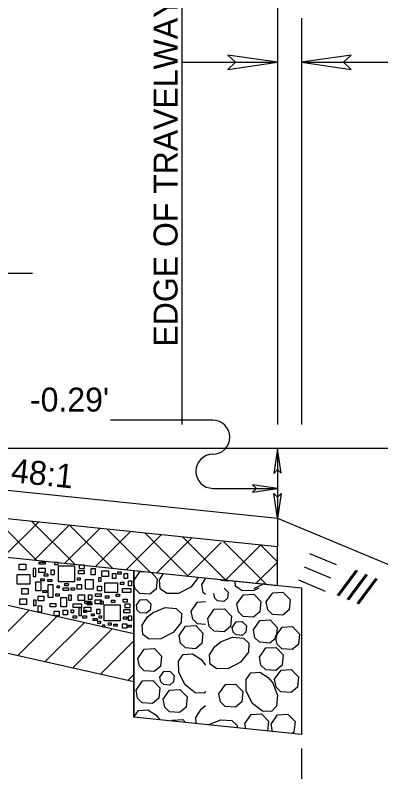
# Model space of a CAD drawing. Extents: x 6561 to 6787, y 19927 to 20919.
# Drawn here: x 6709.58 to 6717.22, y 20861.89 to 20877.71 of the extents above; entities that cross this region are included whole.
import ezdxf

# ---------------------------------------------------------------- set-up
doc = ezdxf.new("R2010")
doc.units = 0
for name, color, linetype in [('Level 1', 7, 'Continuous'), ('Level 10', 7, 'Continuous'), ('Level 3', 7, 'Continuous'), ('Level 4', 7, 'Continuous'), ('Level 5', 7, 'Continuous'), ('Level 7', 7, 'Continuous'), ('Level 8', 7, 'Continuous')]:
    doc.layers.add(name, color=color, linetype=linetype)

msp = doc.modelspace()

# ---------------------------------------------------------------- linework, layer by layer
at = {"layer": 'Level 1'}
for p, q in [((6713.057, 20879.65), (6713.057, 20869.15)), ((6715.057, 20879.65), (6715.057, 20869.15)), ((6715.557, 20877.65), (6715.557, 20869.15)), ((6713.057, 20876.726), (6715.057, 20876.726)), ((6715.557, 20876.726), (6717.557, 20876.726)), ((6703.419, 20872.316), (6709.936, 20872.316)), ((6713.708, 20869.242), (6711.572, 20869.242)), ((6779.047, 20868.65), (6628.473, 20868.65)), ((6715.057, 20868.65), (6715.057, 20867.192)), ((6713.708, 20867.817), (6715.057, 20867.817)), ((6715.557, 20862.377), (6715.557, 20854.582))]:
    msp.add_line(p, q, dxfattribs=at)
for points in [[(6715.057, 20876.726), (6714.018, 20876.876), (6714.178, 20876.726), (6714.018, 20876.576)], [(6715.557, 20876.726), (6716.596, 20876.576), (6716.436, 20876.726), (6716.596, 20876.876)], [(6715.057, 20868.65), (6714.985, 20868.13), (6715.059, 20868.211), (6715.135, 20868.131)], [(6715.057, 20867.817), (6714.537, 20867.889), (6714.618, 20867.815), (6714.538, 20867.739)], [(6715.057, 20867.192), (6714.985, 20867.711), (6715.059, 20867.631), (6715.135, 20867.711)]]:
    msp.add_lwpolyline(points, close=True, dxfattribs=at)
for centre, start, end in [((6713.708, 20868.886), 270, 90), ((6713.708, 20868.173), 90, 270)]:
    msp.add_arc(centre, 0.356, start, end, dxfattribs=at)
at = {"layer": 'Level 10'}
for p, q in [((6712.057, 20864.778), (6701.057, 20867.246)), ((6701.057, 20866.246), (6712.057, 20863.778)), ((6712.057, 20866.1), (6712.057, 20863.033)), ((6709.052, 20864.452), (6709.869, 20865.268)), ((6709.63, 20864.322), (6710.446, 20865.139)), ((6710.207, 20864.193), (6711.024, 20865.009)), ((6710.785, 20864.063), (6711.602, 20864.88)), ((6712.057, 20863.778), (6712.057, 20864.778)), ((6711.362, 20863.933), (6712.057, 20864.628)), ((6711.94, 20863.804), (6712.057, 20863.921))]:
    msp.add_line(p, q, dxfattribs=at)
at = {"layer": 'Level 3'}
for p, q in [((6715.057, 20866.592), (6701.057, 20868.05)), ((6701.057, 20867.246), (6715.057, 20865.787)), ((6710.031, 20866.311), (6709.134, 20867.209)), ((6710.063, 20867.112), (6709.335, 20866.383)), ((6710.821, 20866.229), (6709.923, 20867.126)), ((6710.703, 20867.045), (6709.975, 20866.317)), ((6711.61, 20866.146), (6710.712, 20867.044)), ((6711.344, 20866.978), (6710.615, 20866.25)), ((6711.984, 20866.912), (6711.256, 20866.183)), ((6712.399, 20866.064), (6711.501, 20866.962)), ((6712.625, 20866.845), (6711.896, 20866.116)), ((6713.189, 20865.982), (6712.291, 20866.88)), ((6713.265, 20866.778), (6712.537, 20866.05)), ((6713.966, 20865.912), (6713.08, 20866.797)), ((6713.881, 20866.687), (6713.177, 20865.983)), ((6714.821, 20865.812), (6713.923, 20866.71)), ((6714.703, 20866.628), (6713.975, 20865.9)), ((6715.057, 20866.283), (6714.712, 20866.627)), ((6715.057, 20865.787), (6715.057, 20866.592)), ((6715.057, 20866.275), (6714.615, 20865.833))]:
    msp.add_line(p, q, dxfattribs=at)
at = {"layer": 'Level 4'}
for p, q in [((6701.057, 20867.246), (6712.057, 20866.1)), ((6712.057, 20864.778), (6701.057, 20867.246)), ((6712.057, 20866.1), (6712.057, 20864.778))]:
    msp.add_line(p, q, dxfattribs=at)
for points in [[(6710.206, 20866.229), (6710.077, 20866.229), (6710.077, 20866.276), (6710.206, 20866.276)], [(6710.399, 20866.221), (6710.473, 20866.221), (6710.473, 20866.268), (6710.399, 20866.268)], [(6709.663, 20866.232), (6709.8, 20866.232), (6709.8, 20866.114), (6709.663, 20866.114)], [(6710.01, 20866.138), (6709.951, 20866.138), (6709.951, 20865.973), (6710.01, 20865.973)], [(6710.069, 20866.15), (6710.202, 20866.15), (6710.202, 20866.056), (6710.069, 20866.056)], [(6710.324, 20866.017), (6710.399, 20866.017), (6710.399, 20866.103), (6710.324, 20866.103)], [(6710.485, 20866.197), (6710.819, 20866.197), (6710.819, 20865.863), (6710.485, 20865.863)], [(6711.019, 20866.032), (6710.897, 20866.032), (6710.897, 20866.099), (6711.019, 20866.099)], [(6711.027, 20866.213), (6710.917, 20866.213), (6710.917, 20866.142), (6711.027, 20866.142)], [(6711.251, 20866.005), (6711.164, 20866.005), (6711.164, 20866.138), (6711.251, 20866.138)], [(6711.387, 20866.094), (6711.525, 20866.094), (6711.525, 20865.976), (6711.387, 20865.976)], [(6709.882, 20865.816), (6709.615, 20865.816), (6709.615, 20866.016), (6709.882, 20866.016)], [(6710.185, 20866.029), (6710.256, 20866.029), (6710.256, 20865.982), (6710.185, 20865.982)], [(6710.882, 20865.946), (6710.937, 20865.946), (6710.937, 20865.899), (6710.882, 20865.899)], [(6711.325, 20865.954), (6711.369, 20865.954), (6711.369, 20865.867), (6711.325, 20865.867)], [(6711.614, 20866.033), (6711.681, 20866.033), (6711.681, 20865.931), (6711.614, 20865.931)], [(6711.725, 20866.068), (6711.795, 20866.068), (6711.795, 20866.021), (6711.725, 20866.021)], [(6711.857, 20866.033), (6711.924, 20866.033), (6711.924, 20865.931), (6711.857, 20865.931)], [(6710.112, 20865.675), (6710.01, 20865.675), (6710.01, 20865.859), (6710.112, 20865.859)], [(6710.115, 20865.927), (6710.185, 20865.927), (6710.185, 20865.88), (6710.115, 20865.88)], [(6710.257, 20865.914), (6710.34, 20865.914), (6710.34, 20865.871), (6710.257, 20865.871)], [(6710.269, 20865.804), (6710.363, 20865.804), (6710.363, 20865.533), (6710.269, 20865.533)], [(6710.454, 20865.781), (6710.493, 20865.781), (6710.493, 20865.734), (6710.454, 20865.734)], [(6710.613, 20865.825), (6710.684, 20865.825), (6710.684, 20865.777), (6710.613, 20865.777)], [(6710.96, 20865.71), (6710.87, 20865.71), (6710.87, 20865.804), (6710.96, 20865.804)], [(6711.043, 20865.911), (6711.204, 20865.911), (6711.204, 20865.71), (6711.043, 20865.71)], [(6711.718, 20865.639), (6711.451, 20865.639), (6711.451, 20865.84), (6711.718, 20865.84)], [(6711.779, 20865.852), (6711.85, 20865.852), (6711.85, 20865.805), (6711.779, 20865.805)], [(6711.944, 20865.884), (6712.01, 20865.884), (6712.01, 20865.781), (6711.944, 20865.781)], [(6709.714, 20865.721), (6709.851, 20865.721), (6709.851, 20865.603), (6709.714, 20865.603)], [(6710.158, 20865.683), (6710.229, 20865.683), (6710.229, 20865.636), (6710.158, 20865.636)], [(6710.693, 20865.679), (6710.579, 20865.679), (6710.579, 20865.734), (6710.693, 20865.734)], [(6710.747, 20865.738), (6710.817, 20865.738), (6710.817, 20865.691), (6710.747, 20865.691)], [(6711.384, 20865.675), (6711.294, 20865.675), (6711.294, 20865.769), (6711.384, 20865.769)], [(6711.991, 20865.642), (6711.823, 20865.642), (6711.823, 20865.721), (6711.991, 20865.721)], [(6709.674, 20865.509), (6709.812, 20865.509), (6709.812, 20865.391), (6709.674, 20865.391)], [(6709.967, 20865.486), (6710.01, 20865.486), (6710.01, 20865.36), (6709.967, 20865.36)], [(6710.175, 20865.466), (6710.057, 20865.466), (6710.057, 20865.561), (6710.175, 20865.561)], [(6710.425, 20865.612), (6710.496, 20865.612), (6710.496, 20865.565), (6710.425, 20865.565)], [(6710.528, 20865.537), (6710.65, 20865.537), (6710.65, 20865.337), (6710.528, 20865.337)], [(6710.748, 20865.474), (6710.701, 20865.474), (6710.701, 20865.588), (6710.748, 20865.588)], [(6710.89, 20865.588), (6711.027, 20865.588), (6711.027, 20865.47), (6710.89, 20865.47)], [(6711.109, 20865.592), (6711.176, 20865.592), (6711.176, 20865.49), (6711.109, 20865.49)], [(6711.372, 20865.4), (6711.251, 20865.4), (6711.251, 20865.486), (6711.372, 20865.486)], [(6711.255, 20865.608), (6711.372, 20865.608), (6711.372, 20865.557), (6711.255, 20865.557)], [(6711.461, 20865.569), (6711.532, 20865.569), (6711.532, 20865.522), (6711.461, 20865.522)], [(6711.587, 20865.479), (6711.658, 20865.479), (6711.658, 20865.432), (6711.587, 20865.432)], [(6711.689, 20865.601), (6711.76, 20865.601), (6711.76, 20865.553), (6711.689, 20865.553)], [(6711.834, 20865.498), (6711.917, 20865.498), (6711.917, 20865.435), (6711.834, 20865.435)], [(6710.057, 20865.36), (6710.128, 20865.36), (6710.128, 20865.231), (6710.057, 20865.231)], [(6710.426, 20865.337), (6710.305, 20865.337), (6710.305, 20865.411), (6710.426, 20865.411)], [(6710.96, 20865.325), (6710.791, 20865.325), (6710.791, 20865.404), (6710.96, 20865.404)], [(6710.963, 20865.321), (6710.904, 20865.321), (6710.904, 20865.156), (6710.963, 20865.156)], [(6711.022, 20865.333), (6711.155, 20865.333), (6711.155, 20865.239), (6711.022, 20865.239)], [(6711.159, 20865.412), (6711.03, 20865.412), (6711.03, 20865.459), (6711.159, 20865.459)], [(6711.176, 20865.384), (6711.082, 20865.384), (6711.082, 20865.427), (6711.176, 20865.427)], [(6711.352, 20865.404), (6711.426, 20865.404), (6711.426, 20865.451), (6711.352, 20865.451)], [(6711.438, 20865.38), (6711.772, 20865.38), (6711.772, 20865.046), (6711.438, 20865.046)], [(6711.98, 20865.396), (6711.87, 20865.396), (6711.87, 20865.325), (6711.98, 20865.325)], [(6710.391, 20865.25), (6710.493, 20865.25), (6710.493, 20865.152), (6710.391, 20865.152)], [(6710.67, 20865.172), (6710.579, 20865.172), (6710.579, 20865.266), (6710.67, 20865.266)], [(6710.799, 20865.215), (6710.748, 20865.215), (6710.748, 20865.278), (6710.799, 20865.278)], [(6710.786, 20865.149), (6710.857, 20865.149), (6710.857, 20865.101), (6710.786, 20865.101)], [(6710.994, 20865.152), (6711.065, 20865.152), (6711.065, 20865.105), (6710.994, 20865.105)], [(6711.015, 20865.27), (6711.07, 20865.27), (6711.07, 20865.223), (6711.015, 20865.223)], [(6711.172, 20865.195), (6711.227, 20865.195), (6711.227, 20865.148), (6711.172, 20865.148)], [(6711.277, 20865.2), (6711.352, 20865.2), (6711.352, 20865.286), (6711.277, 20865.286)], [(6711.329, 20865.148), (6711.384, 20865.148), (6711.384, 20865.101), (6711.329, 20865.101)], [(6711.972, 20865.215), (6711.85, 20865.215), (6711.85, 20865.282), (6711.972, 20865.282)], [(6711.944, 20865.153), (6712.01, 20865.153), (6712.01, 20865.05), (6711.944, 20865.05)], [(6711.21, 20865.097), (6711.293, 20865.097), (6711.293, 20865.054), (6711.21, 20865.054)], [(6711.302, 20865.038), (6711.357, 20865.038), (6711.357, 20864.991), (6711.302, 20864.991)], [(6711.526, 20865.003), (6711.581, 20865.003), (6711.581, 20864.955), (6711.526, 20864.955)], [(6711.913, 20864.893), (6711.823, 20864.893), (6711.823, 20864.987), (6711.913, 20864.987)], [(6711.842, 20865.129), (6711.913, 20865.129), (6711.913, 20865.082), (6711.842, 20865.082)], [(6711.406, 20864.964), (6711.446, 20864.964), (6711.446, 20864.917), (6711.406, 20864.917)], [(6711.638, 20864.98), (6711.709, 20864.98), (6711.709, 20864.932), (6711.638, 20864.932)], [(6711.946, 20864.959), (6712.001, 20864.959), (6712.001, 20864.912), (6711.946, 20864.912)]]:
    msp.add_lwpolyline(points, close=True, dxfattribs=at)
at = {"layer": 'Level 5'}
for p, q in [((6712.057, 20863.033), (6712.057, 20866.1)), ((6712.057, 20866.1), (6715.557, 20865.735)), ((6715.557, 20865.735), (6715.557, 20862.669)), ((6715.557, 20862.669), (6712.057, 20863.033))]:
    msp.add_line(p, q, dxfattribs=at)
for points in [[(6712.048, 20865.879), (6712.183, 20866.071), (6712.283, 20866.076)], [(6712.417, 20866.062), (6712.547, 20865.928), (6712.525, 20865.711), (6712.393, 20865.601), (6712.181, 20865.616), (6712.081, 20865.713), (6712.049, 20865.879)], [(6713.41, 20865.959), (6713.246, 20865.749), (6712.988, 20865.62), (6712.746, 20865.616), (6712.609, 20865.713), (6712.596, 20865.906), (6712.679, 20866.035)], [(6713.475, 20865.808), (6713.557, 20865.925)], [(6713.557, 20865.594), (6713.508, 20865.642), (6713.475, 20865.808)], [(6714.03, 20865.894), (6714.011, 20865.878), (6713.883, 20865.887), (6713.858, 20865.912)], [(6714.669, 20865.732), (6714.561, 20865.678), (6714.318, 20865.674), (6714.181, 20865.771), (6714.174, 20865.879)], [(6714.771, 20865.817), (6714.564, 20865.714)], [(6713.947, 20865.732), (6714.026, 20865.649), (6714.013, 20865.519), (6713.934, 20865.453), (6713.807, 20865.462), (6713.747, 20865.52), (6713.727, 20865.62)], [(6714.823, 20865.443), (6714.958, 20865.635), (6715.172, 20865.647), (6715.321, 20865.492), (6715.3, 20865.275), (6715.167, 20865.165), (6714.955, 20865.18), (6714.856, 20865.277), (6714.823, 20865.443)], [(6712.11, 20865.371), (6712.19, 20865.486), (6712.319, 20865.493), (6712.409, 20865.4), (6712.396, 20865.27), (6712.316, 20865.204), (6712.189, 20865.213), (6712.129, 20865.271), (6712.11, 20865.371)], [(6714.211, 20865.4), (6714.346, 20865.591), (6714.561, 20865.603), (6714.71, 20865.448), (6714.688, 20865.232), (6714.556, 20865.121), (6714.344, 20865.137), (6714.244, 20865.233), (6714.212, 20865.4)], [(6712.458, 20865.224), (6712.71, 20865.323), (6712.941, 20865.304), (6713.05, 20865.199), (6713.047, 20865.012), (6712.88, 20864.799), (6712.623, 20864.67), (6712.38, 20864.666), (6712.243, 20864.763), (6712.23, 20864.956), (6712.341, 20865.129), (6712.468, 20865.23)], [(6713.255, 20865.248), (6713.389, 20865.44), (6713.557, 20865.449)], [(6713.557, 20864.973), (6713.387, 20864.985), (6713.287, 20865.082), (6713.255, 20865.248)], [(6713.6, 20865.095), (6713.734, 20865.287), (6713.949, 20865.299), (6714.098, 20865.144), (6714.076, 20864.927), (6713.944, 20864.817), (6713.732, 20864.832), (6713.632, 20864.929), (6713.6, 20865.095)], [(6714.113, 20864.91), (6714.194, 20865.025), (6714.323, 20865.032), (6714.412, 20864.94), (6714.399, 20864.809), (6714.32, 20864.743), (6714.192, 20864.752), (6714.133, 20864.81), (6714.113, 20864.91)], [(6714.554, 20864.861), (6714.688, 20865.052), (6714.903, 20865.064), (6715.052, 20864.909), (6715.03, 20864.693), (6714.898, 20864.582), (6714.686, 20864.598), (6714.586, 20864.694), (6714.554, 20864.861)], [(6713.002, 20864.742), (6713.136, 20864.934), (6713.351, 20864.946), (6713.5, 20864.791), (6713.478, 20864.574), (6713.346, 20864.464), (6713.134, 20864.479), (6713.034, 20864.576), (6713.002, 20864.742)], [(6715.02, 20864.722), (6715.154, 20864.913), (6715.369, 20864.925), (6715.518, 20864.771), (6715.496, 20864.554), (6715.364, 20864.444), (6715.152, 20864.459), (6715.052, 20864.556), (6715.02, 20864.722)], [(6713.867, 20864.604), (6714.119, 20864.703), (6714.35, 20864.684), (6714.46, 20864.579), (6714.456, 20864.392), (6714.289, 20864.179), (6714.032, 20864.05), (6713.789, 20864.046), (6713.652, 20864.143), (6713.639, 20864.336), (6713.75, 20864.509), (6713.877, 20864.61)], [(6712.139, 20864.262), (6712.274, 20864.454), (6712.489, 20864.466), (6712.638, 20864.311), (6712.616, 20864.094), (6712.484, 20863.984), (6712.272, 20863.999), (6712.172, 20864.096), (6712.14, 20864.262)], [(6713.557, 20863.567), (6713.526, 20863.535), (6713.339, 20863.538), (6713.126, 20863.705), (6712.997, 20863.963), (6712.993, 20864.205), (6713.09, 20864.342), (6713.283, 20864.355), (6713.456, 20864.244), (6713.557, 20864.118)], [(6714.68, 20864.288), (6714.815, 20864.479), (6715.029, 20864.492), (6715.179, 20864.337), (6715.157, 20864.12), (6715.024, 20864.01), (6714.812, 20864.025), (6714.713, 20864.122), (6714.68, 20864.288)], [(6712.601, 20863.87), (6712.682, 20863.985), (6712.811, 20863.993), (6712.9, 20863.9), (6712.888, 20863.77), (6712.808, 20863.703), (6712.681, 20863.713), (6712.621, 20863.771), (6712.602, 20863.87)], [(6714.96, 20863.743), (6715.06, 20863.492), (6715.04, 20863.261), (6714.935, 20863.151), (6714.748, 20863.154), (6714.535, 20863.321), (6714.406, 20863.579), (6714.402, 20863.821), (6714.499, 20863.958), (6714.692, 20863.971), (6714.865, 20863.86), (6714.966, 20863.733)], [(6714.998, 20863.826), (6715.132, 20864.017), (6715.347, 20864.029), (6715.496, 20863.875), (6715.475, 20863.658), (6715.342, 20863.547), (6715.13, 20863.563), (6715.03, 20863.66), (6714.998, 20863.826)], [(6712.102, 20863.598), (6712.236, 20863.789), (6712.451, 20863.802), (6712.6, 20863.647), (6712.579, 20863.43), (6712.446, 20863.32), (6712.234, 20863.335), (6712.134, 20863.432), (6712.102, 20863.598)], [(6713.835, 20863.52), (6713.969, 20863.712), (6714.184, 20863.724), (6714.333, 20863.569), (6714.312, 20863.352), (6714.179, 20863.242), (6713.967, 20863.257), (6713.867, 20863.354), (6713.835, 20863.52)], [(6712.67, 20863.408), (6712.804, 20863.6), (6713.019, 20863.612), (6713.168, 20863.457), (6713.147, 20863.24), (6713.014, 20863.13), (6712.802, 20863.145), (6712.702, 20863.242), (6712.67, 20863.408)], [(6713.362, 20862.897), (6713.353, 20863.028), (6713.464, 20863.201), (6713.557, 20863.276)], [(6712.057, 20863.033), (6712.057, 20863.034), (6712.154, 20863.171), (6712.348, 20863.184), (6712.521, 20863.073), (6712.597, 20862.977)], [(6714.373, 20862.897), (6714.508, 20863.088), (6714.722, 20863.1), (6714.871, 20862.946), (6714.851, 20862.742)], [(6714.926, 20862.889), (6715.061, 20863.08), (6715.275, 20863.092), (6715.425, 20862.938), (6715.403, 20862.721), (6715.365, 20862.689)], [(6712.85, 20862.951), (6712.864, 20862.97), (6713.079, 20862.983), (6713.139, 20862.921)], [(6713.623, 20862.879), (6713.875, 20862.979), (6714.106, 20862.959), (6714.216, 20862.855), (6714.215, 20862.808)], [(6713.615, 20862.871), (6713.633, 20862.886)], [(6714.394, 20862.79), (6714.373, 20862.897)], [(6714.957, 20862.731), (6714.926, 20862.889)]]:
    msp.add_lwpolyline(points, dxfattribs=at)
at = {"layer": 'Level 7'}
msp.add_line((6715.057, 20867.192), (6723.057, 20863.858), dxfattribs=at)
for points in [[(6715.728, 20866.454), (6716.282, 20866.223)], [(6715.613, 20866.177), (6716.167, 20865.947)], [(6715.498, 20865.901), (6716.052, 20865.67)]]:
    msp.add_lwpolyline(points, dxfattribs=at)
at = {"layer": 'Level 8'}
for p, q in [((6701.057, 20868.65), (6715.057, 20867.192)), ((6715.057, 20866.592), (6701.057, 20868.05)), ((6715.057, 20867.192), (6715.057, 20866.592))]:
    msp.add_line(p, q, dxfattribs=at)

# ---------------------------------------------------------------- texts
at = {"layer": 'Level 1'}
for s, rotation, p in [('EDGE OF TRAVELWAY', 90, (6712.97, 20870.781)), ('48:1', 354.0531, (6709.474, 20867.949))]:
    msp.add_text(s, height=0.5, rotation=rotation, dxfattribs=at).set_placement(p)
msp.add_text("-0.29'", height=0.5, dxfattribs=at).set_placement((6709.887, 20869.423))
at = {"layer": 'Level 7'}
msp.add_text('///', height=0.6, rotation=337.3802, dxfattribs=at).set_placement((6716.297, 20865.593))

doc.saveas('drawing.dxf')
